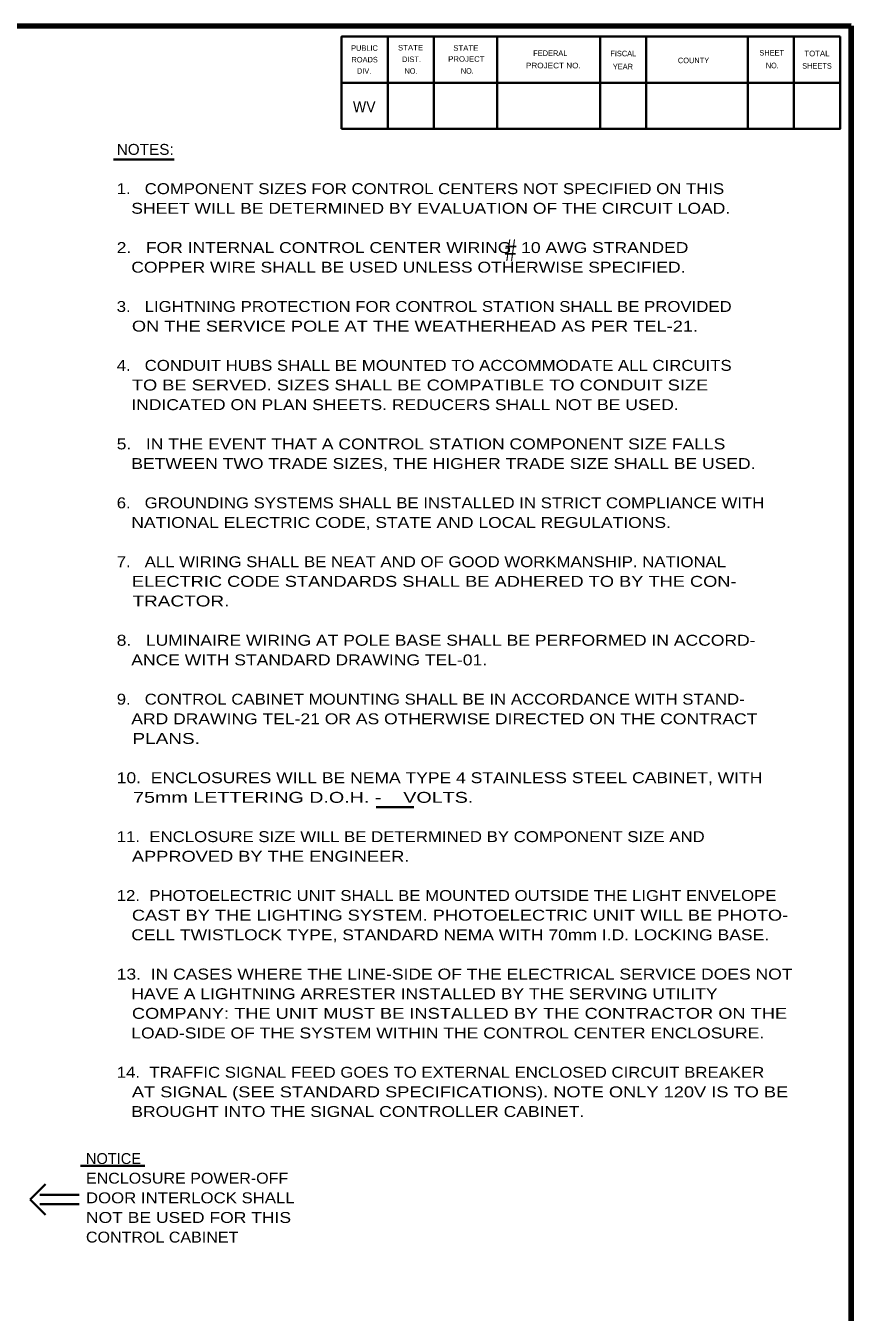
# Model space of a CAD drawing. Extents: x -35 to 821, y -18 to 526.
# Drawn here: x 587.3 to 814.4, y 165.4 to 519.2 of the extents above; entities that cross this region are included whole.
import ezdxf

# ---------------------------------------------------------------- set-up
doc = ezdxf.new("R2010")
doc.units = 0
doc.header["$LTSCALE"] = 1.2
doc.layers.add('1', color=7, linetype='Continuous', lineweight=53)
doc.layers.add('61', color=7, linetype='Continuous', lineweight=35)

msp = doc.modelspace()

# ---------------------------------------------------------------- linework, layer by layer
at = {"layer": '1', "lineweight": 158}
msp.add_line((814.433, -6.884), (814.433, 519.216), dxfattribs=at)
at = {"layer": '1', "lineweight": 13}
msp.add_line((814.433, -6.884), (814.433, 519.216), dxfattribs=at)
at = {"layer": '1', "lineweight": 35}
for p, q in [((611.495, 482.424), (628.181, 482.424)), ((683.761, 304.272), (694.113, 304.272)), ((602.344, 205.713), (620.122, 205.713)), ((588.502, 196.399), (592.745, 200.641)), ((588.502, 196.399), (592.745, 192.156)), ((591.198, 197.705), (601.998, 197.705)), ((591.198, 195.093), (601.998, 195.093))]:
    msp.add_line(p, q, dxfattribs=at)
at = {"layer": '1', "lineweight": 158}
msp.add_lwpolyline([(814.433, 519.216), (22.733, 519.116), (22.833, -6.884)], dxfattribs=at)
at = {"layer": '61'}
for p, q in [((686.933, 516.216), (686.933, 490.816)), ((699.633, 516.216), (699.633, 490.816)), ((717.033, 516.216), (717.033, 490.816)), ((745.333, 516.216), (745.333, 490.816)), ((758.033, 516.216), (758.033, 490.816)), ((785.933, 516.216), (785.933, 490.816)), ((798.633, 516.216), (798.633, 490.816)), ((811.333, 503.516), (674.233, 503.516))]:
    msp.add_line(p, q, dxfattribs=at)
for points in [[(811.333, 516.216), (674.233, 516.216), (674.233, 490.816)], [(811.333, 516.216), (811.333, 490.816), (674.233, 490.816)]]:
    msp.add_lwpolyline(points, dxfattribs=at)

# ---------------------------------------------------------------- texts
at = {"layer": '1'}
for s, height, width, p in [('WV', 3.048, 0.95, (677.333, 495.416)), ('NOTES:', 3, 1.05, (612.345, 483.707)), ('1.   COMPONENT SIZES FOR CONTROL CENTERS NOT SPECIFIED ON THIS', 3, 1.15, (612.345, 472.907)), ('   SHEET WILL BE DETERMINED BY EVALUATION OF THE CIRCUIT LOAD.', 3, 1.2, (612.345, 467.507)), ('#', 6, 0.7, (719.179, 454.521)), ('2.   FOR INTERNAL CONTROL CENTER WIRING  10 AWG STRANDED', 3, 1.2, (612.345, 456.707)), ('   COPPER WIRE SHALL BE USED UNLESS OTHERWISE SPECIFIED.', 3, 1.2, (612.345, 451.307)), ('3.   LIGHTNING PROTECTION FOR CONTROL STATION SHALL BE PROVIDED', 3, 1.15, (612.345, 440.507)), ('   ON THE SERVICE POLE AT THE WEATHERHEAD AS PER TEL-21.', 3, 1.25, (612.345, 435.107)), ('4.   CONDUIT HUBS SHALL BE MOUNTED TO ACCOMMODATE ALL CIRCUITS', 3, 1.15, (612.345, 424.307)), ('   TO BE SERVED. SIZES SHALL BE COMPATIBLE TO CONDUIT SIZE ', 3, 1.25, (612.345, 418.907)), ('   INDICATED ON PLAN SHEETS. REDUCERS SHALL NOT BE USED.', 3, 1.2, (612.345, 413.507)), ('5.   IN THE EVENT THAT A CONTROL STATION COMPONENT SIZE FALLS', 3, 1.2, (612.345, 402.707)), ('   BETWEEN TWO TRADE SIZES, THE HIGHER TRADE SIZE SHALL BE USED.', 3, 1.2, (612.345, 397.307)), ('6.   GROUNDING SYSTEMS SHALL BE INSTALLED IN STRICT COMPLIANCE WITH', 3, 1.15, (612.345, 386.507)), ('   NATIONAL ELECTRIC CODE, STATE AND LOCAL REGULATIONS.', 3, 1.2, (612.345, 381.107)), ('7.   ALL WIRING SHALL BE NEAT AND OF GOOD WORKMANSHIP. NATIONAL', 3, 1.15, (612.345, 370.307)), ('   ELECTRIC CODE STANDARDS SHALL BE ADHERED TO BY THE CON-', 3, 1.25, (612.345, 364.907)), ('   TRACTOR.', 3, 1.3, (612.345, 359.507)), ('8.   LUMINAIRE WIRING AT POLE BASE SHALL BE PERFORMED IN ACCORD-', 3, 1.2, (612.345, 348.707)), ('   ANCE WITH STANDARD DRAWING TEL-01.', 3, 1.2, (612.345, 343.307)), ('9.   CONTROL CABINET MOUNTING SHALL BE IN ACCORDANCE WITH STAND-', 3, 1.15, (612.345, 332.507)), ('   ARD DRAWING TEL-21 OR AS OTHERWISE DIRECTED ON THE CONTRACT ', 3, 1.2, (612.345, 327.107)), ('   PLANS.', 3, 1.3, (612.345, 321.707)), ('10.  ENCLOSURES WILL BE NEMA TYPE 4 STAINLESS STEEL CABINET, WITH', 3, 1.2, (612.345, 310.907)), ('   75mm LETTERING D.O.H. -    VOLTS.', 3, 1.35, (612.345, 305.507)), ('11.  ENCLOSURE SIZE WILL BE DETERMINED BY COMPONENT SIZE AND', 3, 1.15, (612.345, 294.707)), ('   APPROVED BY THE ENGINEER.', 3, 1.25, (612.345, 289.307)), ('12.  PHOTOELECTRIC UNIT SHALL BE MOUNTED OUTSIDE THE LIGHT ENVELOPE', 3, 1.15, (612.345, 278.507)), ('   CAST BY THE LIGHTING SYSTEM. PHOTOELECTRIC UNIT WILL BE PHOTO-', 3, 1.25, (612.345, 273.107)), ('   CELL TWISTLOCK TYPE, STANDARD NEMA WITH 70mm I.D. LOCKING BASE.', 3, 1.2, (612.345, 267.707)), ('13.  IN CASES WHERE THE LINE-SIDE OF THE ELECTRICAL SERVICE DOES NOT', 3, 1.2, (612.345, 256.907)), ('   HAVE A LIGHTNING ARRESTER INSTALLED BY THE SERVING UTILITY', 3, 1.2, (612.345, 251.507)), ('   COMPANY: THE UNIT MUST BE INSTALLED BY THE CONTRACTOR ON THE', 3, 1.25, (612.345, 246.107)), ('   LOAD-SIDE OF THE SYSTEM WITHIN THE CONTROL CENTER ENCLOSURE.', 3, 1.2, (612.345, 240.707)), ('14.  TRAFFIC SIGNAL FEED GOES TO EXTERNAL ENCLOSED CIRCUIT BREAKER', 3, 1.15, (612.345, 229.907)), ('   AT SIGNAL (SEE STANDARD SPECIFICATIONS). NOTE ONLY 120V IS TO BE', 3, 1.25, (612.345, 224.507)), ('   BROUGHT INTO THE SIGNAL CONTROLLER CABINET.', 3, 1.2, (612.345, 219.107)), ('ENCLOSURE POWER-OFF', 3, 1.1, (603.881, 200.774)), ('DOOR INTERLOCK SHALL', 3, 1.15, (603.881, 195.374)), ('NOT BE USED FOR THIS', 3, 1.2, (603.881, 189.974)), ('CONTROL CABINET', 3, 1.1, (603.881, 184.574))]:
    msp.add_text(s, height=height, dxfattribs=dict(at, width=width)).set_placement(p)
msp.add_text('NOTICE', height=3, dxfattribs=at).set_placement((603.881, 206.174))
at = {"layer": '61'}
for s, height, rotation, p in [('PUBLIC', 1.525, 0.033, (676.833, 512.316)), ('ROADS', 1.525, 0.124, (676.933, 509.116)), ('DIST.', 1.525, 0.056, (690.833, 509.216)), ('FEDERAL', 1.523, 0.007, (726.933, 510.916)), ('FISCAL', 1.525, 359.942, (748.133, 510.816)), ('COUNTY', 1.523, 0.069, (766.733, 508.916)), ('SHEET', 1.525, 0.059, (789.133, 511.016)), ('DIV.', 1.525, 359.932, (678.433, 506.016)), ('YEAR', 1.523, 0.105, (748.833, 507.216)), ('SHEETS', 1.523, 359.959, (800.933, 507.416))]:
    msp.add_text(s, height=height, rotation=rotation, dxfattribs=at).set_placement(p)
for s, rotation, width, p in [('STATE', 0.059, 1.05, (689.733, 512.416)), ('STATE', 0.059, 1.05, (704.933, 512.316)), ('PROJECT', 359.908, 1.05, (703.533, 509.316)), ('TOTAL', 359.926, 1.05, (801.533, 510.816)), ('NO.', 359.852, 0.9, (691.533, 506.016)), ('NO.', 0.225, 0.9, (707.033, 506.016)), ('PROJECT NO.', 359.922, 1.1, (724.933, 507.516)), ('NO.', 359.852, 0.9, (790.933, 507.516))]:
    msp.add_text(s, height=1.525, rotation=rotation, dxfattribs=dict(at, width=width)).set_placement(p)

doc.saveas('drawing.dxf')
